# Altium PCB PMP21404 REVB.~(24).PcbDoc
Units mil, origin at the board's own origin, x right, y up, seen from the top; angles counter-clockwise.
Board outline 2750 x 3000 mil, 2 copper layers (Top Layer, Bottom Layer), stack 62 mil thick; 50 components, 25 nets, 104 pads, 31 vias.
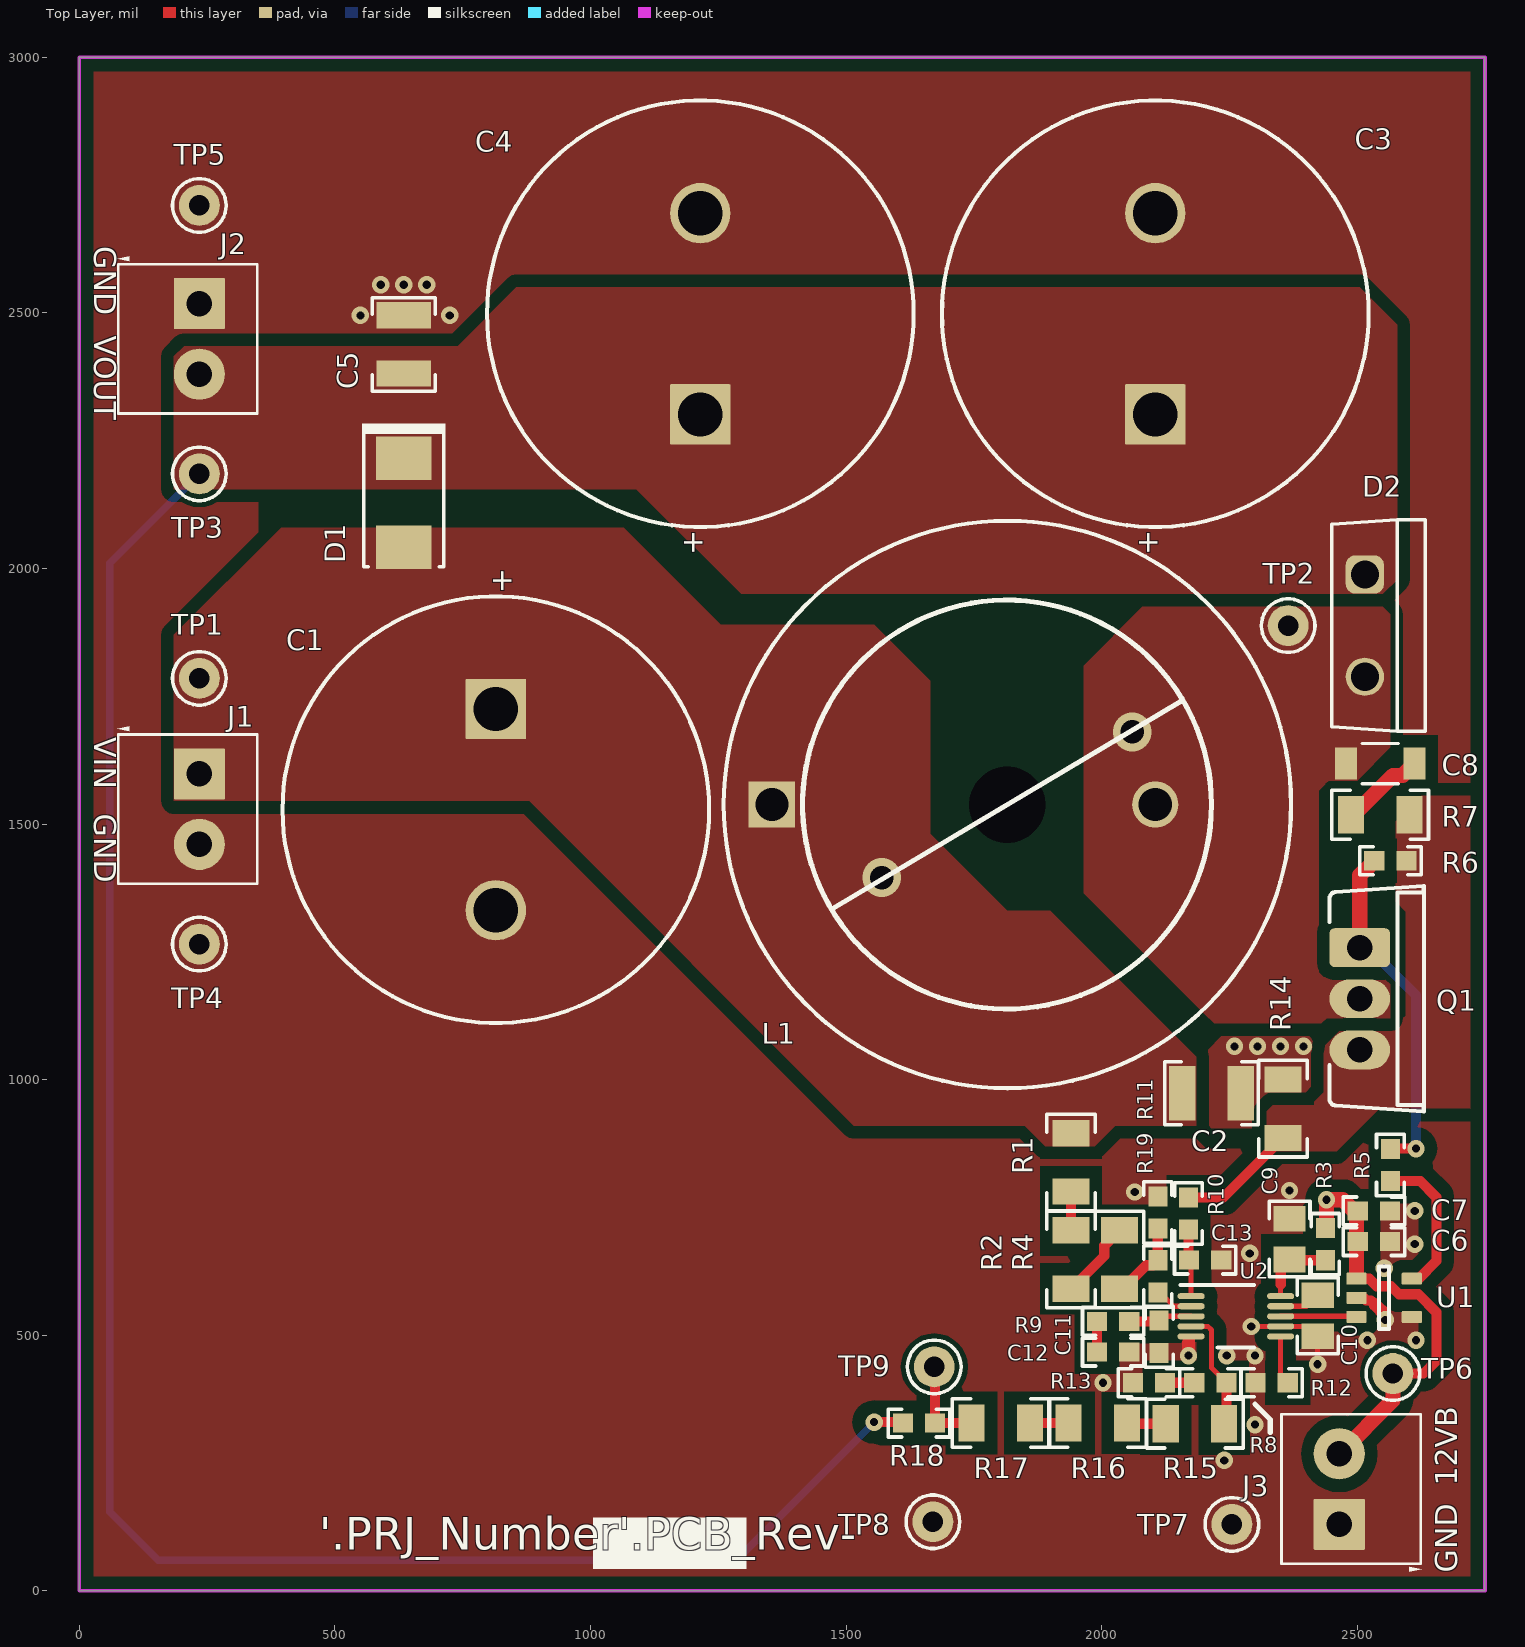
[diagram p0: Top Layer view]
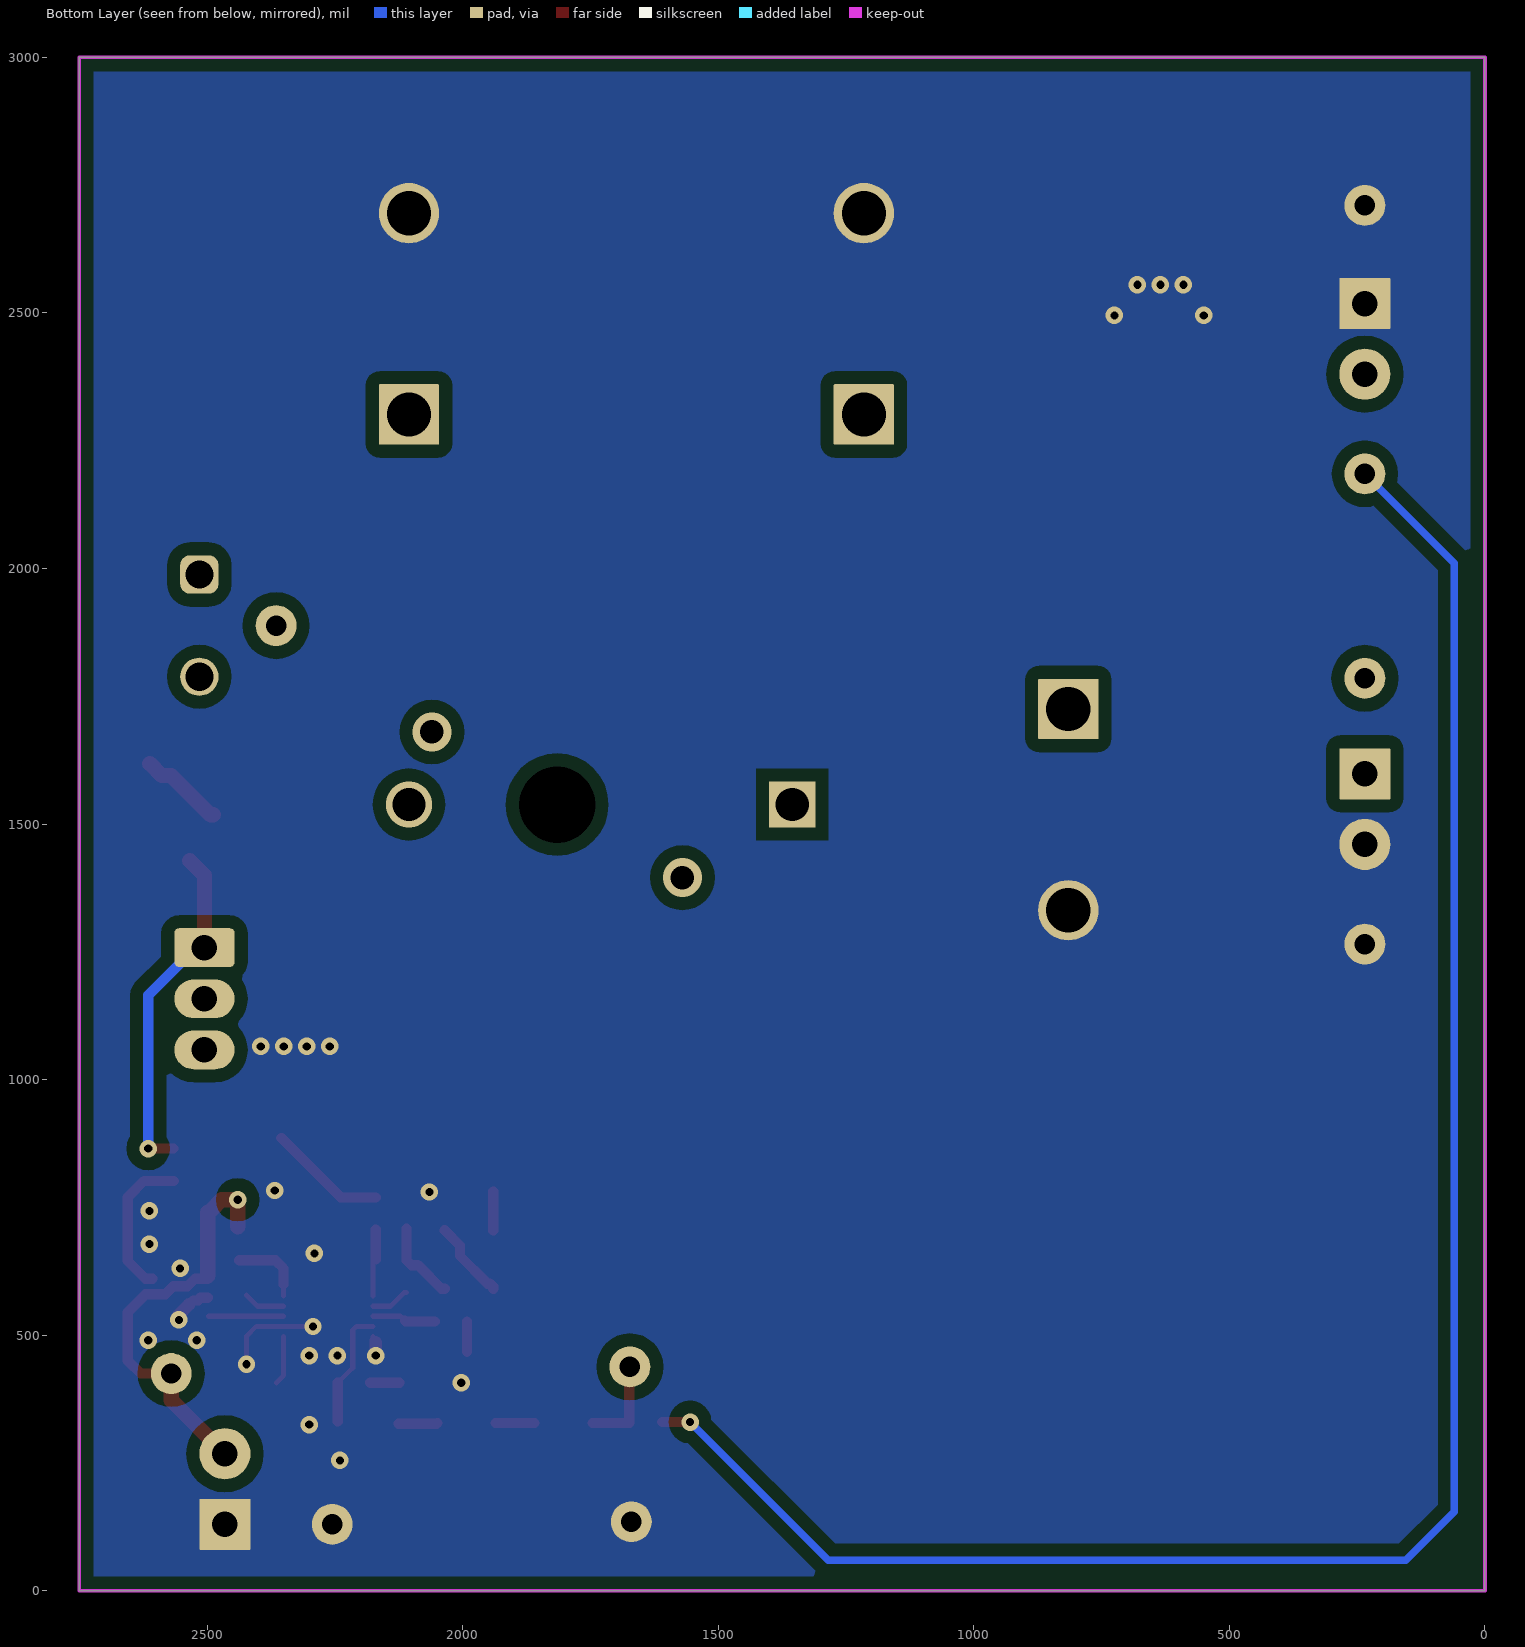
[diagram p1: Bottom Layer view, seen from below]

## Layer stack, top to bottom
Top Solder: solder mask 0.4, Solder Resist, Dk 3.5
Top Layer: signal copper 1.4
Dielectric1: core 59.2, FR-4, Dk 4.8
Bottom Layer: signal copper 1.4
Bottom Solder: solder mask 0.4, Solder Resist, Dk 3.5

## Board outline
0,0 2750,0 2750,3000 0,3000

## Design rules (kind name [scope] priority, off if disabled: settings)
AcuteAngle [All] p1: minimum=4.50000000000000E+0001 checktracksonly=FALSE
AssemblyTestPointUsage [All] p1: valid=2
BoardOutlineClearance BoardOutlineClearance_MountingHoles [OnCopper and InComponentClass('Mounting Holes')] p1: gap=40 ignorepadtopadclearanceinfootprint=FALSE
BoardOutlineClearance BoardOutlineClearance_Poly [OnCopper and IsPoly] p2: gap=25 ignorepadtopadclearanceinfootprint=FALSE
BoardOutlineClearance [OnCopper and Not InComponentClass('Logo') and not InComponentClass('FiducialMark') and not InRegion(1000,500,4000,800) and not InPoly] p3: gap=50 ignorepadtopadclearanceinfootprint=FALSE
Clearance Clearance_Keepouts [((IsTrack Or IsArc) And Not InPoly) And IsFree and IsKeepOut vs ((IsTrack Or IsArc) And Not InPoly) And IsFree and IsKeepOut] p1: gap=0 ignorepadtopadclearanceinfootprint=FALSE
Clearance Clearance_Poly [InPolygon] p2: gap=25 ignorepadtopadclearanceinfootprint=FALSE except(0: Arc-Hole Track-Hole SMDPad-Hole THPad-Hole Via-Hole Fill-Hole Poly-Hole Region-Hole Text-Hole)
Clearance Clearance_FiducialMark [IsKeepOut and InComponentClass('FiducialMark') vs IsPad and InComponentClass('FiducialMark')] p3: gap=0 ignorepadtopadclearanceinfootprint=FALSE
Clearance [All] p4: gap=7.87 ignorepadtopadclearanceinfootprint=FALSE except(0: Arc-Hole Track-Hole SMDPad-Hole THPad-Hole Via-Hole Fill-Hole Poly-Hole Region-Hole Text-Hole)
ComponentClearance ComponentClearance_MountingHoles_FiducialMarks [InComponentClass('Mounting Holes') vs InComponentClass('FiducialMark')] p1: gap=50 collisioncheckmode=3 verticalgap=10 showdistances=FALSE
ComponentClearance ComponentClearance_Shunt [InComponentClass('Header') vs InComponentClass('Shunt')] p2: gap=0 collisioncheckmode=3 verticalgap=0 showdistances=FALSE
ComponentClearance ComponentClearance_Logo [InComponentClass('Logo')] p3: gap=50 collisioncheckmode=3 verticalgap=10 showdistances=FALSE
ComponentClearance ComponentClearance_ScrewToNut [(HasFootprint('NY PMS 440 0025 PH')) vs (HasFootprint('Keystone_1902C'))] p4: gap=5 collisioncheckmode=3 verticalgap=10 showdistances=FALSE
ComponentClearance ComponentClearance_MountingHoles [InComponentClass('Mounting Holes')] p5: gap=250 collisioncheckmode=3 verticalgap=100000 showdistances=FALSE
ComponentClearance ComponentClearance_SmallPassives [HasFootprint('0201*') or HasFootprint('0402*') or HasFootprint('0508') or HasFootprint('0603*') or HasFootprint('0612') or HasFootprint('0805*') or HasFootprint('0815*') or HasFootprint('0830*') or HasFootprint('1206*') or HasFootprint('1210*') or HasFootprint('1808*') or HasFootprint('1812*') or HasFootprint('1825*') or HasFootprint('2010*') or HasFootprint('2220*') or HasFootprint('2225*') or HasFootprint('2512*') or HasFootprint('2728*') or HasFootprint('3518*') vs HasFootprint('0201*') or HasFootprint('0402*') or HasFootprint('0508') or HasFootprint('0603*') or HasFootprint('0612') or HasFootprint('0805*') or HasFootprint('0815*') or HasFootprint('0830*') or HasFootprint('1206*') or HasFootprint('1210*') or HasFootprint('1808*') or HasFootprint('1812*') or HasFootprint('1825*') or HasFootprint('2010*') or HasFootprint('2220*') or HasFootprint('2225*') or HasFootprint('2512*') or HasFootprint('2728*') or HasFootprint('3518*')] p6: gap=14.96 collisioncheckmode=3 verticalgap=10 showdistances=FALSE
ComponentClearance ComponentClearance_THtoSMT [IsThruComponent vs IsSMTComponent] p7: gap=40 collisioncheckmode=3 verticalgap=30 showdistances=FALSE
ComponentClearance ComponentClearance_THtoTH [IsThruComponent vs IsThruComponent] p8: gap=30 collisioncheckmode=3 verticalgap=30 showdistances=FALSE
ComponentClearance [All] p9: gap=30 collisioncheckmode=3 verticalgap=10 showdistances=FALSE
DiffPairsRouting [All] p1: maxlimit=100 minlimit=10 mostfreqgap=10 toplayer_minwidth=15 toplayer_maxwidth=15 toplayer_prefwidth=15 bottomlayer_minwidth=15 bottomlayer_maxwidth=15 bottomlayer_prefwidth=15 maxuncoupledlength=1000
FabricationTestPointUsage TestPointUsage [All] p1: valid=2 allowmultiple=FALSE
FabricationTestpoint Testpoint [All] p1: side=3 testpointundercomponent=TRUE minsize=40 maxsize=100 preferedsize=60 minholesize=0 maxholesize=40 preferedholesize=32 testpointgrid=1 allowsidetop=TRUE allowsidebottom=TRUE usegrid=TRUE gridtolerance=0.01
FanoutControl Fanout_LCC [IsLCC] p1: bgadir=Out bgaviamode=Centered fanoutstyle=Auto fanoutdirection=Alternating viagrid=1 // Fanout_LCC (Default Rule)
FanoutControl Fanout_BGA [IsBGA] p2: bgadir=Out bgaviamode=Centered fanoutstyle=Auto fanoutdirection=Alternating viagrid=1 // Fanout_BGA (Default Rule)
FanoutControl Fanout_Default [All] p4: bgadir=Out bgaviamode=Centered fanoutstyle=Auto fanoutdirection=Alternating viagrid=1 // Fanout_Default (Default Rule)
FanoutControl Fanout_Small [(CompPinCount < 5)] p5: bgadir=Out bgaviamode=Centered fanoutstyle=Auto fanoutdirection=OutThenIn viagrid=1 // Fanout_Small (Default Rule)
HoleSize [All] p1: absolutevalues=TRUE maxlimit=251 minlimit=7.87 maxpercent=80.000 minpercent=20.000
MinimumAnnularRing MinimumAnnularRing_ThermalPadVias [IsVia and InAnyComponent] p1: minimumring=5.91
MinimumAnnularRing [All] p2: minimumring=8
MinimumSolderMaskSliver MinimumSolderMaskSliver_Logo [InComponentClass('Logo') vs InComponentClass('Logo')] p1: minsoldermaskwidth=0.7
MinimumSolderMaskSliver [All] p2: minsoldermaskwidth=3.94
PlaneConnect [All] p1: planeconnectstyle=Direct reliefexpansion=10 reliefentries=4 reliefconductorwidth=10 reliefairgap=10
PolygonConnect [All] p1: connectstyle=Direct reliefconductorwidth=10 reliefentries=4 polygonreliefangle="90 Angle" airgapwidth=10
RoutingVias ThermalPadVias [IsVia and InAnyComponent] p1: holewidth=7.87 width=19.68 viastyle="Through Hole" minholewidth=7.87 minwidth=19.68 maxholewidth=12.99 maxwidth=23.62
RoutingVias [All] p2: holewidth=16 width=34 viastyle="Through Hole" minholewidth=7.87 minwidth=26 maxholewidth=40 maxwidth=65
SilkToBoardRegionClearance [Not ((IsComment or IsDesignator) And (Hide <> 'False')) and not InRegion(1000,500,4000,800)] p1:
SilkToSilkClearance SilkToSilkClearance_Pb-FreeLogo [(HasFootprint('Pb-Free_Overlay_Medium') OR HasFootprint('Pb-Free_Overlay_Small')) vs (HasFootprint('Pb-Free_Overlay_Medium') OR HasFootprint('Pb-Free_Overlay_Small'))] p1: silktosilkclearance=0
SilkToSilkClearance [All] p2: silktosilkclearance=0
SilkToSolderMaskClearance SilkToComponentPadClearance [(IsPad or IsFill or IsRegion) and InAnycomponent] p1: minsilkscreentomaskgap=0 clearancetoexposedcopper=TRUE
SilkToSolderMaskClearance "Silk to Solder Mask Opening" [All] p2: minsilkscreentomaskgap=0 clearancetoexposedcopper=FALSE
SolderMaskExpansion [All] p1: expansion=1.97
Width [All] p1: maxlimit=100 minlimit=6 preferedwidth=10 checkconnectedcopper=TRUE
15 further rules are at their usual default settings.

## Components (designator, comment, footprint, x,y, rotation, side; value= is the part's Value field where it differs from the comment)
C1 "LLS2W560MELY" Nichicon_2000x2500_Snap 815,1528.07 r270 top value=56uF
C2 "CGA6L1X7T2J104K160AC" 1210_200 2215,973.07 r0 top value=0.1uF
C3 "LLS2W560MELY" Nichicon_2000x2500_Snap 2105,2498.07 r90 top value=56uF
C4 "" Nichicon_2000x2500_Snap 1215,2498.07 r90 top
C5 "CGA6L1X7T2J104K160AC" 1210_200 635,2438.07 r90 top
C6 "C0603C104K5RACAUTO" 0603 2532.68,683.07 r0 top value=0.1uF
C7 "CGA3E1X7R1C105K080AC" 0603 2532.68,743.07 r0 top value=1uF
C8 "C3216C0G2E153J160AA" 1206_190 2545,1618.07 r0 top
C9 "CGA4J3X7R1H105K125AB" 0805_HV 2367.68,688.07 r90 top value=1uF
C10 "CGA4J3X7R1H105K125AB" 0805_HV 2422.68,538.07 r270 top value=1uF
C11 "GRM188R71H471KA01D" 0603 2112.68,496.93 r270 top value=470pF
C12 "CGA3E3X7R1H474K080AB" 0603 2022.68,466.93 r0 top value=0.47uF
C13 "GRM188R71H102JA01D" 0603 2202.68,646.93 r0 top value=1000pF
D1 "STTH3L06U" SMB 635,2128.07 r270 top value=600V
D2 "C3D03060A" TO-220-2 2515,1888.07 r270 top value=600V
J1 "Receptacle_2x1" TERM_BLK_ED555-2DS 235,1598.07 r270 top
J2 "Receptacle_2x1" TERM_BLK_ED555-2DS 235,2518.07 r270 top
J3 "Receptacle_2x1" TERM_BLK_ED555-2DS 2465,130 r90 top
L1 "RL-1256-3-470" Renco_RL1256-3_Pitch_750 1815,1538.07 r0 top value=470uH
Q1 "IPP60R299CPXKSA1" TO-220AB 2505,1158.07 r270 top value=600V
R1 "CRCW1206150KFKEA" 1206 1940,838.07 r90 top value=150k
R2 "CRCW1206150KFKEA" 1206 1940,648.07 r90 top value=150k
R3 "CRCW060310R0FKEA" 0603 2437.68,678.07 r270 top value=10.0
R4 "CRCW1206150KFKEA" 1206 2035,648.07 r90 top value=150k
R5 "CRCW06033R30JNEA" 0603 2565,833.07 r90 top value=3.3
R6 "CRCW0603100KFKEA" 0603 2565,1428.07 r180 top value=100k
R7 "CRCW1206150KFKEA" 1206 2545,1518.07 r0 top
R8 "RG1608P-2611-B-T5" 0603 2212.68,406.93 r0 top value=2.61k
R9 "CRCW060310K0FKEA" 0603 2022.68,526.93 r0 top value=10.0k
R10 "Resistor" 0603 2170,738.07 r270 top value=221
R11 "RT0603BRD074K59L" 0603 2110,740 r270 top value=4.59k
R12 "CRCW0603169KFKEA" 0603 2332.68,406.93 r0 top value=169k
R13 "RMCF0603ZT0R00" 0603 2092.68,406.93 r0 top value=0
R14 "WSLP1206R0150FEA" 1206 2355,943.07 r270 top value=0.015
R15 "CRCW1206150KFKEA" 1206 2182.68,326.93 r0 top value=150k
R16 "CRCW1206150KFKEA" 1206 1992.68,328.07 r0 top value=150k
R17 "CRCW1206150KFKEA" 1206 1802.68,328.07 r0 top value=150k
R18 "Resistor" 0603 1642.68,328.07 r0 top value=49.9
R19 "RMCF0603ZT0R00" 0603 2110,615 r90 top value=0
TP1 "5000" Keystone5000 235,1785 r90 top
TP2 "5000" Keystone5000 2365,1888.07 r90 top
TP3 "5000" Keystone5000 235,2185 r90 top
TP4 "5001" Keystone5001 235,1265 r90 top
TP5 "5001" Keystone5001 235,2710 r90 top
TP6 "5000" Keystone5000 2570,425 r0 top
TP7 "5001" Keystone5001 2255,130 r0 top
TP8 "5001" Keystone5001 1670,135 r90 top
TP9 "5000" Keystone5000 1672.68,438.07 r90 top
U1 "UCC27517AQDBVRQ1" DBV0005A_N 2552.68,573.07 r0 top
U2 "LM3481QMM/NOPB" DGS0010A_N 2262.68,536.93 r0 top

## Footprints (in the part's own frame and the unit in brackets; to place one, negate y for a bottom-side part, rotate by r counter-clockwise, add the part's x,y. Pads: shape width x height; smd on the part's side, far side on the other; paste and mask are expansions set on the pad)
0603 [mm] "0603 from SM-752 data"
  rect 1x0.95 smd: 1(-0.8,0) 2(0.8,0)
  silkscreen extent -1.52,-0.69 1.52,0.69, body extent -0.87,-0.47 0.87,0.47, height 1
0805_HV [mil] "0805 with 30mil clearance between pads"
  rect 50x63 smd: 1(-40,0) 2(40,0)
  silkscreen extent -74,-40 74,40, body extent -43,-29 43,29, height 57
1206 [mm] "1206 from SM-752 data"
  rect 1.3x1.85 smd: 1(-1.45,0) 2(1.45,0)
  silkscreen extent -2.4,-1.21 2.4,1.21, body extent -1.7,-0.9 1.7,0.9, height 1.35
1206_190 [mm] "1206_190"
  rect 1.1x1.6 smd: 1(-1.7,0) 2(1.7,0)
  silkscreen extent -0.9,-1 0.9,1, body extent -1.75,-0.95 1.75,0.95, height 1.9
1210_200 [mm] "1210"
  rect 1.3x2.7 smd: 1(-1.45,0) 2(1.45,0)
  silkscreen extent -2.32,-1.57 2.32,1.57, body extent -1.7,-1.35 1.7,1.35, height 2
DBV0005A_N [mm] "SOT23, 5-Leads, Body 2.9x1.6mm, Pitch 0.95mm, Lead Span 2.8mm, IPC Medium Density"
  rrect17% 1x0.6 smd: 1(-1.375,0.95) 2(-1.375,0) 3(-1.375,-0.95) 4(1.375,-0.95) 5(1.375,0.95)
  silkscreen extent -0.25,-1.55 0.25,1.55, body extent -1.42,-1.46 1.42,1.46, height 1.09
DGS0010A_N [mm] "TSSOP, 10-Leads, Body 3x3mm, Pitch 0.5mm, IPC Medium Density"
  oval 1.35x0.3 smd: 1(-2.225,1) 2(-2.225,0.5) 3(-2.225,0) 4(-2.225,-0.5) 5(-2.225,-1) 6(2.225,-1) 7(2.225,-0.5) 8(2.225,0) 9(2.225,0.5) 10(2.225,1)
  silkscreen extent -2.75,-1.55 0.9,1.55, body extent -2.45,-1.5 2.45,1.5, height 0.96
Keystone5000 [mil] "For Keystone 500x miniature loop terminals"
  round 80 hole 40: 1(0,0)
  silkscreen extent -52,-52 52,52, body extent -49,-49 49,49, height 182
Keystone5001 [mil] "For Keystone 500x miniature loop terminals"
  round 80 hole 40: 1(0,0)
  silkscreen extent -52,-52 52,52, body extent -49,-49 49,49, height 182
Nichicon_2000x2500_Snap [mm]
  rrect3% 3x3 hole 2.2: 1(-5,0)
  round 3 hole 2.2: 2(5,0)
  silkscreen extent -10.6,-10.6 10.6,10.6, body extent -10.5,-10.5 10.51,10.5, height 27.01
Renco_RL1256-3_Pitch_750 [mm] "RENCO"
  rect 2.3x2.3 hole 1.65 paste+0 mask+0.05: 1(-11.684,0)
  round 2.3 hole 1.65 paste+0 mask+0.05: 2(7.366,0)
  round 1 hole 3.8 unplated: MH(0,0)
  silkscreen extent -14.08,-14.1 14.11,14.1, body extent -13.97,-13.97 13.97,13.97, height 21.59
SMB [mil] "Molded Diode, 2-Leads, Body 5.4x3.6mm, IPC Medium Density, based on OnSemi component dimensions"
  rect 85x107.99 smd: 1(-87.01,0) 2(87.01,0)
  silkscreen extent -155,-82 125,82, body extent -106,-71 106,71, height 91
TERM_BLK_ED555-2DS [mil]
  rrect4% 100x100 hole 50: 1(0,0)
  round 100 hole 50: 2(138,0)
  silkscreen extent -93,-161 215,113, body extent -69,-150 207,106, height 323
TO-220-2 [mm] "CREE"
  rrect50% 1.9x1.9 hole 1.4: 1(-2.54,0)
  round 1.9 hole 1.4: 2(2.54,0)
  silkscreen extent -5.25,-1.64 5.26,3.01, body extent -5.21,-1.57 5.21,3.12, height 19.47
TO-220AB [mil] "Copied from Altium's version of TO3B"
  rrect25% 76x118.11 hole 50: 1(-100,0)
  oval 76x118.11 hole 50: 2(0,0) 3(100,0)
  silkscreen extent -221,-59 221,126, body extent -221,-59 221,126, height 765

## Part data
C1 C3: library part CMP-0010119-2, "CAP, AL, 56 uF, 450 V, +/- 20%, TH", Cap_Case=20x25mm, Manufacturer=Nichicon, Supplier Part Number 1=493-2592-ND, Tolerance_%=20%, Value1=Unknown, Value2=450V, ValueDisplayed=56uF
C2: library part CMP-0009140-2, "CAP, CERM, 0.1 uF, 630 V, +/- 10%, X7R, AEC-Q200 Grade 1, 1210", Cap_Case=1210, Manufacturer=TDK, Supplier Part Number 1=445-7116-1-ND, TempCo=X7R, Tolerance_%=10%, Value1=Unknown, Value2=630V, ValueDisplayed=0.1uF
C4: library part CMP-0010119-2, "CAP, AL, DNP", Cap_Case=20x25mm, Tolerance_%=20%, Value1=Unknown, ValueDisplayed=DNP
C5: library part CMP-0009140-2, "CAP, CERM, DNP", Cap_Case=1210, Value1=Unknown, ValueDisplayed=DNP
C6: library part CMP-0079602-1, "CAP, CERM, 0.1 µF, 50 V,+/- 10%, X7R, AEC-Q200 Grade 1, 0603", Cap_Case=0603, Manufacturer=Kemet, Supplier Part Number 1=399-6856-1-ND, TempCo=X7R, Tolerance_%=10%, Value2=50V, ValueDisplayed=0.1µF
C7: library part CMP-0079607-1, "CAP, CERM, 1 µF, 16 V,+/- 10%, X7R, AEC-Q200 Grade 1, 0603", Cap_Case=0603, Manufacturer=TDK, Supplier Part Number 1=445-12539-1-ND, TempCo=X7R, Tolerance_%=10%, Value2=16V, ValueDisplayed=1µF
C8: library part CMP-0008644-2, "CAP, CERM, DNP", Cap_Case=1206, Value1=Unknown, ValueDisplayed=DNP
C9 C10: library part CMP-0007976-2, "CAP, CERM, 1 uF, 50 V, +/- 10%, X7R, AEC-Q200 Grade 1, 0805", Cap_Case=0805, Manufacturer=TDK, Supplier Part Number 1=445-6961-1-ND, TempCo=X7R, Tolerance_%=10%, Value1="0.008782 ohm", Value2=50V, ValueDisplayed=1uF
C11: library part CMP-0007455-4, "CAP, CERM, 470 pF, 50 V, +/- 10%, X7R, 0603", Cap_Case=0603, Manufacturer=MuRata, Supplier Part Number 1=490-1489-1-ND, TempCo=X7R, Tolerance_%=10%, Value1=Unknown, Value2=50V, ValueDisplayed=470pF
C12: library part CMP-0007096-4, "CAP, CERM, 0.47 uF, 50 V, +/- 10%, X7R, AEC-Q200 Grade 1, 0603", Cap_Case=0603, Manufacturer=TDK, Supplier Part Number 1=810-CGA3E3X7R1H474K080AB, TempCo=X7R, Tolerance_%=10%, Value1="0.01064 ohm", Value2=50V, ValueDisplayed=0.47uF
C13: library part CMP-0007431-4, "CAP, CERM, 1000 pF, 50 V, +/- 5%, X7R, 0603", Cap_Case=0603, Manufacturer=MuRata, Supplier Part Number 1=490-9733-1-ND, TempCo=X7R, Tolerance_%=5%, Value1=Unknown, Value2=50V, ValueDisplayed=1000pF
D1: library part CMP-0077014-1, "Diode, Ultrafast, 600 V, 3 A, SMB", Manufacturer=STMicroelectronics, Supplier Part Number 1=497-3771-1-ND, Value1=3A, Value2=1.3V
D2: library part CMP-0079543-1, "Diode, Schottky, 600 V, 11 A, AEC-Q101, TH", Manufacturer=Cree, Supplier Part Number 1=941-C3D03060A, Value1=11A, Value2=V
J1 J2 J3: library part CMP-0074913-1, "Terminal Block, 3.5mm Pitch, 2x1, TH", Color=Grey, Current_A=6A, Manufacturer="On-Shore Technology", PartNumber=ED555/2DS, Supplier Part Number 1=ED1514-ND, Voltage_V=150V
L1: library part CMP-0077831-1, "Inductor, 470 µH, 4 A, 0.187 ohm, TH", Manufacturer="Renco Electronics", Value1="0.187 ohm", Value2=4A, ValueDisplayed=470µH
Q1: library part CMP-0001176-3, "MOSFET, N-CH, 600 V, 11 A, TO-220AB", Alternate Manufacturer=None, Manufacturer="Infineon Technologies", Supplier Part Number 1=IPP60R299CPXKSA1-ND, Value2="22 nC"
R1 R2 R4 R15 R16 R17: library part CMP-0016639-3, "RES, 150 k, 1%, 0.25 W, AEC-Q200 Grade 0, 1206", Manufacturer=Vishay-Dale, Power_W=250mW, Supplier Part Number 1=541-150KFCT-ND, TempCo="100 ppm/C", Tolerance_%=1%, Value2=0.25W, Value_Code=150k
R3: library part CMP-0022003-4, "RES, 10.0, 1%, 0.1 W, AEC-Q200 Grade 0, 0603", Manufacturer=Vishay-Dale, Power_W=100mW, Supplier Part Number 1=541-10.0HCT-ND, TempCo="100 ppm/C", Tolerance_%=1%, Value2=0.1W, Value_Code=10R0, ValueDisplayed=10.0
R5: library part CMP-0025805-4, "RES, 3.3, 5%, 0.1 W, AEC-Q200 Grade 0, 0603", Manufacturer=Vishay-Dale, Power_W=100mW, Supplier Part Number 1=541-3.3GCT-ND, TempCo="200 ppm/C", Tolerance_%=5%, Value2=0.1W, Value_Code=3R30, ValueDisplayed=3.3
R6: library part CMP-0021990-4, "RES, 100 k, 1%, 0.1 W, AEC-Q200 Grade 0, 0603", Manufacturer=Vishay-Dale, Power_W=100mW, Supplier Part Number 1=541-100KHCT-ND, TempCo="100 ppm/C", Tolerance_%=1%, Value2=0.1W, Value_Code=100k
R7: library part CMP-0016639-3, "RES, DNP, 1206", TempCo="100 ppm/C", ValueDisplayed=DNP
R8: library part CMP-0023494-3, "RES, 2.61 k, 0.1%, 0.1 W, 0603", Manufacturer="Susumu Co Ltd", Power_W=100mW, Supplier Part Number 1=RG16P2.61KBCT-ND, TempCo="25 ppm/C", Tolerance_%=0.1%, Value2=0.1W, Value_Code=2k61, ValueDisplayed=2.61k
R9: library part CMP-0021998-4, "RES, 10.0 k, 1%, 0.1 W, AEC-Q200 Grade 0, 0603", Manufacturer=Vishay-Dale, Power_W=100mW, Supplier Part Number 1=541-10.0KHCT-ND, TempCo="100 ppm/C", Tolerance_%=1%, Value2=0.1W, Value_Code=10k0, ValueDisplayed=10.0k
R10: library part CMP-0022217-5, "RES, 221, 1%, 0.1 W, AEC-Q200 Grade 0, 0603", Manufacturer=Vishay-Dale, PartNumber=CRCW0603221RFKEA, Power_W=100mW, Supplier Part Number 1=541-221HCT-ND, TempCo="100 ppm/C", Tolerance_%=1%, Value2=0.1W, Value_Code=221R, ValueDisplayed=221
R11: library part CMP-0024297-2, "RES, 4.59 k, 0.1%, 0.1 W, 0603", Manufacturer="Yageo America", Power_W=100mW, TempCo="25 ppm/C", Tolerance_%=0.1%, Value2=0.1W, Value_Code=4k59, ValueDisplayed=4.59k
R12: library part CMP-0022077-4, "RES, 169 k, 1%, 0.1 W, AEC-Q200 Grade 0, 0603", Manufacturer=Vishay-Dale, Power_W=100mW, Supplier Part Number 1=541-169KHCT-ND, TempCo="100 ppm/C", Tolerance_%=1%, Value2=0.1W, Value_Code=169k
R13 R19: library part CMP-0023343-3, "RES, 0, 1%, 0.1 W, AEC-Q200 Grade 0, 0603", Manufacturer="Stackpole Electronics Inc", Power_W=100mW, Supplier Part Number 1=RMCF0603ZT0R00CT-ND, TempCo=ppm/C, Tolerance_%=1%, Value2=0.1W, Value_Code=0
R14: library part CMP-0018571-2, "RES, 0.015, 1%, 1 W, 1206", Manufacturer=Vishay-Dale, Power_W=1W, Supplier Part Number 1=WSLP-.015CT-ND, TempCo="75 ppm/C", Tolerance_%=1%, Value_Code=R015, ValueDisplayed=0.015
R18: library part CMP-0022448-4, "RES, 49.9, 1%, 0.1 W, AEC-Q200 Grade 0, 0603", Manufacturer=Vishay-Dale, PartNumber=CRCW060349R9FKEA, Power_W=100mW, Supplier Part Number 1=541-49.9HCT-ND, TempCo="100 ppm/C", Tolerance_%=1%, Value2=0.1W, Value_Code=49R9, ValueDisplayed=49.9
TP1 TP2 TP3 TP6 TP9: library part CMP-0055137-1, "Test Point, Miniature, Red, TH", Color=Red, Manufacturer=Keystone, Supplier Part Number 1=36-5000-ND
TP4 TP5 TP7 TP8: library part CMP-0055138-1, "Test Point, Miniature, Black, TH", Color=Black, Manufacturer=Keystone, Supplier Part Number 1=36-5001-ND
U1: library part CMP-0066947-1, "4A/4A Single Channel High-speed Low-side Gate Driver, DBV0005A (SOT-23-5)", Alternate Manufacturer="Texas Instruments"
U2: library part CMP-0071928-2, "High Efficiency Low-Side N-Channel Controller for Switching Regulators, AEC-Q100 Grade 1, 10-pin Mini SOIC, 1000 Reel", Alternate Manufacturer="Texas Instruments", Alternate PartNumber=LM3481QMMX/NOPB

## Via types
v1: diameter 34, hole 16, Top Layer to Bottom Layer, 29 vias
v2: diameter 76, hole 46, Top Layer to Bottom Layer, 2 vias

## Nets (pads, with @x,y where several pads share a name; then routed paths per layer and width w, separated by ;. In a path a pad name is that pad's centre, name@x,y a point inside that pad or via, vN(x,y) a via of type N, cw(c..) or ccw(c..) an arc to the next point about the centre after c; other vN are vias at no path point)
GND: C1.2 C2.2 C3.2 C4.2 C5.2 C6.2 C7.2 C9.2 C10.2 C11.2 C12.2 C13.2 J1.2 J2.1 J3.1 R11.1 R12.1 R13.1 R14.1 TP4.1 TP5.1 TP7.1 TP8.1 U1.2 U1.4 U2.5 U2.7 | length 313.6
  Top Layer w10: 2175.08,490.97 U2.5 ; v1(2292.68,516.93) 2292.99,517.25 U2.7 2403.5,517.25 C10.2 v1(2422.68,443.07)
  Top Layer w15: 2170,485.89 2175.08,490.97
  Top Layer w20: U1.2 2513.07,573.07 2513.07,571.93 2517.18,567.82 2527.18,567.82 2535,560
  Top Layer w25: v1(2170,460) 2170,485.89 ; 2535,560 2555,540 v1(2555,530)
  other v1: 2240,255 2300,325 2002.68,406.93 2245,460 2300,460 2520,490 2615,490 2552.68,630.57 2290,660 2612.68,678.07 2612.68,743.07 2065,780 2367.68,783.07 2260,1065 2305,1065 2350,1065 2395,1065 550,2495 725,2495 590,2555 635,2555 680,2555
NetC1_1: C1.1 C2.1 D1.2 J1.1 L1.1 R1.2 TP1.1
  other v2: 1570,1395
NetC3_1: C3.1 C4.1 C5.1 D1.1 D2.1 J2.2 R18.1 TP3.1 | length 3802.9
  Top Layer w20: v1(1555,330) R18.1@1609.25,330
  Bottom Layer w15: TP3.1 60,2010 60,155 155,60 1285,60 v1(1555,330)
NetC6_1: C6.1 C7.1 J3.2 R3.1 TP6.1 U1.1 | length 820.2
  Top Layer w20: U1.1@2498.54,616.42 U1.1 2523.46,610.47 2538.24,595.7 2565.99,595.7 2581.69,580 2620,580 2655,545 2655,450 2630,425 TP6.1
  Top Layer w30: R3.1@2440,711.89 v1(2440,765) 2471.65,765 C7.1@2493.58,743.07 ; J3.2 2570,373 TP6.1 ; U1.1@2498.54,616.42 C7.1@2498.54,740.43
NetC8_1: C8.1 D2.2 L1.2 Q1.2 TP2.1
  other v2: 2060,1680
NetC8_2: C8.2 R7.1 | length 165.4
  Top Layer w30: R7.1 2493.07,1518.07 2570,1595 2588.86,1595 C8.2
NetC9_1: C9.1 R3.2 U2.10 | length 148.4
  Top Layer w10: U2.10 2350.28,599.72
  Top Layer w20: 2350.28,599.72 2350.28,630.67 2366.18,646.57 R3.2
NetC10_1: C10.1 U2.9 | length 81.3
  Top Layer w10: U2.9 2401.22,556.62 C10.1
NetC11_1: C11.1 R9.2 U2.3 | length 125
  Top Layer w10: C11.1 2121.18,536.93 U2.3
  Top Layer w20: R9.2 2111.18,526.93 C11.1
NetC12_1: C12.1 R9.1 | length 60
  Top Layer w20: C12.1 R9.1
NetC13_1: C13.1 R10.2 U2.1 | length 132.4
  Top Layer w10: C13.1@2170,648.11 C13.1 2175.08,643.03 U2.1
  Top Layer w20: C13.1@2170,648.11 R10.2
NetQ1_1: Q1.1 R5.2 R6.2 | length 679.9
  Top Layer w20: R5.2@2565.43,865 v1(2615,865)
  Top Layer w30: Q1.1 2505,1399.57 R6.2
  Bottom Layer w20: Q1.1 2521.93,1258.07 2615,1165 v1(2615,865)
NetQ1_3: Q1.3 R6.1 R7.2 R10.1 R14.2 | length 233.2
  Top Layer w20: R10.1 2238.58,769.57 R14.2
NetR1_1: R1.1 R2.2 | length 75.8
  Top Layer w20: R2.2 R1.1
NetR2_1: R2.1 R4.2 | length 156.2
  Top Layer w20: R2.1 1940,594.57 1946.26,600.83 1950.83,600.83 2005,655 2005,675.16 R4.2
NetR4_1: R4.1 R11.2 R19.2 | length 160
  Top Layer w20: R4.1 2041.42,590.98 2087.07,636.63 2099.98,636.63 2109.84,646.5 R19.2 R11.2
NetR5_1: R5.1 U1.5 | length 290.6
  Top Layer w20: R5.1 2623.43,801.57 2655,770 2655,645 2620.47,610.47 U1.5
NetR8_1: R8.1 R13.2 | length 57
  Top Layer w20: R13.2 R8.1
NetR8_2: R8.2 R15.2 U2.4 | length 233.7
  Top Layer w10: U2.4 2207.75,517.25 2215,510 2215,436.1 R8.2
  Top Layer w20: R15.2@2244.17,331.34 R8.2
NetR12_2: R12.2 U2.6 | length 96.4
  Top Layer w10: U2.6 2350.28,420.83 R12.2
NetR15_1: R15.1 R16.2 | length 76.3
  Top Layer w20: R16.2 2050.9,326.93 R15.1
NetR16_1: R16.1 R17.2 | length 75.8
  Top Layer w20: R17.2 R16.1
NetR17_1: R17.1 R18.2 TP9.1 | length 182
  Top Layer w20: TP9.1 1674.17,436.57 R18.2 R17.1
NetR19_1: R19.1 U2.2 | length 76.2
  Top Layer w10: R19.1 2114.19,583.5 2141.08,556.62 U2.2
NetU1_3: U1.3 U2.8 | length 147
  Top Layer w10: U2.8 U1.3@2497.28,536.93
pads on no net: L1.MH

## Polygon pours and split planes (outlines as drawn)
NetC1_1 on Top Layer "TOP_LAYER_NETC1_1_P002" (solid, remove dead copper, pour order 2): 185,1545 185,1870 395,2080 1065,2080 1815,1330 1900,1330 2185,1045 2185,910.08 2026.34,910.08 1986.26,870 1890,870 1850,910 1515,910 880,1545
NetC8_1 on Top Layer "TOP_LAYER_NETC8_1_P004" (solid, remove dead copper, pour order 4): 2565,1120 2210,1120 1965,1365 1965,1810 2080,1925 2550,1925 2565,1910 2565,1650 2500,1585 2445,1585 2425,1565 2425,1210 2435,1200 2563.83,1200 2565,1198.83
NetC8_1 on Top Layer "TOP_LAYER_NETC8_1_P006" (solid, remove dead copper, pour order 6): 2505,1120 2440,1120 2430,1110 2220,1110 2190,1140 2190,1155 2195,1150 2505,1150
NetC3_1 on Top Layer "TOP_LAYER_NETC3_1_P008" (solid, remove dead copper, pour order 8): 2550,1950 2578.29,1978.29 2578.29,2476.71 2505,2550 855,2550 740,2435 205,2435 185,2415 185,2155 1090,2155 1295,1950
NetQ1_3 on Top Layer "TOP_LAYER_NETQ1_3_P010" (solid, remove dead copper, pour order 10): 2320,860 2320,935 2335,950 2410,950 2435,975 2435,1065 2465,1095 2565,1095 2595,1125 2595,1328.83 2575,1348.83 2575,1505 2625,1555 2750,1555 2750,945 2748.38,943.38 2582.55,943.38 2582.45,943.28 2543.28,943.28 2460,860
NetC1_1 on Top Layer "TOP_LAYER_NETC1_1_P014" (solid, remove dead copper, pour order 14): 1245,1890 1555,1890 1665,1780 1665,1425 1660,1420 1245,1420
GND on Top Layer "TOP_LAYER_GND_P016" (solid, remove dead copper, pour order 16): 0,0 0,3000 2750,3000 2750,0
GND on Bottom Layer "BOTTOM_LAYER_GND_P012" (solid, remove dead copper, pour order 12): 0,0 0,3000 2750,3000 2750,0

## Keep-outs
Keep-Out Layer:
  the board outline again, w7
  text ".Layer_Name" at 577,-858.49 h60

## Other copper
Top Layer:
  pour cut-out: 2200,905 2305,905 2305,865 2205,865 2170,900 2195,900
  pour cut-out: 350,2060 350,2145 440,2145 440,2100 390,2100
  pour cut-out: 2210,1035 2208.55,1036.45 2208.55,1058.55 2235,1085 2235,1100 2180,1100 2165,1085
  text ".Layer_Name" at 577,-858.49 h60
Bottom Layer:
  text ".Layer_Name" at 577,-858.49 h60

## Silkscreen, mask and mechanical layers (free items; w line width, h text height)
Top Overlay:
  circle w10: c1815,1538.07 r400
  region: 1305,143.07 1005,143.07 1005,43.07 1305,43.07
  lines w10: 1475,1335 2155,1740 ; 2300,365 2330,335 2330,310
  text "GND" at 15,2630 h72.83 r270
  text "VOUT" at 15,2455 h72.83 r270
  text "VIN" at 15,1670 h72.83 r270
  text "GND" at 15,1520 h72.83 r270
  text "12VB" at 2710,205 h72.83 r90
  text "'.PRJ_Number'.PCB_Rev-" at 470,58.84 h108.27
  text "GND" at 2710,35 h72.83 r90
  text ".Layer_Name" at 577,-858.49 h60
Bottom Overlay:
  text ".Layer_Name" at 577,-858.49 h60
Top Paste:
  text ".Layer_Name" at 577,-858.49 h60
Bottom Paste:
  text ".Layer_Name" at 577,-858.49 h60
Top Solder:
  text ".Layer_Name" at 577,-858.49 h60
  text ".Layer_Name" at 577,-858.49 h60
Bottom Solder:
  text ".Layer_Name" at 577,-858.49 h60
Drill Guide:
  text ".Layer_Name" at 577,-858.49 h60
M1 Board Outline:
  lines w5: 0,0 2750,0 2750,3000 0,3000 0,0
  lines w7: 0,0 2750,0 2750,3000 0,3000 0,0
  text ".Layer_Name" at 577,-858.49 h60
M2 Board Dimensions:
  rectangle: 125,-400 500,-275
  rectangle: 0,-275 125,-150
  lines w7: 0,-275 1000,-275 ; 125,-400 125,-150 ; 250,-400 250,-150 ; 500,-400 500,-150 ; 750,-400 750,-150 ; 0,-400 0,-150 1000,-150 1000,-400 0,-400
  text ".Layer_Name" at 577,-858.49 h60
M3 3D STEP Top:
  text ".Layer_Name" at 577,-858.49 h60
M4 3D STEP Bottom:
  text ".Layer_Name" at 577,-858.49 h60
M5 Assembly Top:
  lines w10: -292,-930.17 6308,-930.17 ; -292,-726.83 6310,-726.83 ; -292,-523.5 -292,-1133.5 3713,-1133.5 6310,-1133.5 6310,-523.5 -291.5,-523.5 -291.5,-1133.5 1284,-1133.5 ; 2173,-1133.5 2173,-523.5 ; 3440,-726.83 3440,-523.5 ; 4280,-726.83 4280,-523.5 ; 4902,-1140 4902,-937.17
  text "COMPONENTS MARKED 'DNP' SHOULD NOT BE POPULATED." at 1153.5,-318.5 h60
  text "ASSEMBLY VARIANT:" at 1153,-434 h60
  text ".VariantName" at 2189,-434 h60
  text "PCB VIEWED FROM TOP SIDE" at -228.5,-655.67 h60
  text "BOARD #:" at 2248,-655.67 h60
  text ".PRJ_Number" at 2793.5,-655.67 h60
  text "REV:" at 3638,-655.67 h60
  text ".PCB_Rev" at 3929.5,-655.67 h60
  text "SVN REV:" at 4476,-655.67 h60
  text ".VersionControl_RevNumber" at 4982,-655.67 h60
  text "TID #:" at 2248,-859 h60
  text ".TID" at 2793.5,-859 h60
  text "PLOT NAME =" at -228.5,-1064.34 h60
  text ".plot_File_Name" at 577,-1064.34 h60
  text "GENERATED    :" at 2250,-1064.34 h60
  text ".Print_Date" at 3119.5,-1064.34 h60
  text ".Print_Time" at 3848.5,-1064.34 h60
  text "TEXAS INSTRUMENTS" at 5113,-1064.34 h60
M6 Assembly Bottom:
  lines w10: -292.5,-727.33 6309.5,-727.33 ; -290.5,-930.67 6309.5,-930.67 ; 1115.5,-1140.5 1115.5,-937.67 ; 1737.5,-727.33 1737.5,-524 ; 2577.5,-727.33 2577.5,-524 ; 3844.5,-1134 3844.5,-524 ; 4733.5,-1134 6309,-1134 6309,-524 -292.5,-524 -292.5,-1134 2304.5,-1134 6309.5,-1134 6309.5,-524
  text "COMPONENTS MARKED 'DNP' SHOULD NOT BE POPULATED." at 6102,-318 h60
  text ".VariantName" at 5058,-434 h60
  text "ASSEMBLY VARIANT:" at 6097,-434 h60
  text ".VersionControl_RevNumber" at 1035.5,-656.17 h60
  text "SVN REV:" at 1541.5,-656.17 h60
  text ".PCB_Rev" at 2088,-656.17 h60
  text "REV:" at 2379.5,-656.17 h60
  text ".PRJ_Number" at 3224,-656.17 h60
  text "BOARD #:" at 3769.5,-656.17 h60
  text "PCB VIEWED FROM BOTTOM SIDE" at 6246,-656.17 h60
  text ".TID" at 3224,-859.5 h60
  text "TID #:" at 3769.5,-859.5 h60
  text "TEXAS INSTRUMENTS" at 904.5,-1064.84 h60
  text ".Print_Time" at 2169,-1064.84 h60
  text ".Print_Date" at 2898,-1064.84 h60
  text "GENERATED    :" at 3767.5,-1064.84 h60
  text ".plot_File_Name" at 5440.5,-1064.84 h60
  text "PLOT NAME =" at 6246,-1064.84 h60
M9 Title Sheet:
  drawing of 57 lines, arcs and shapes, not listed
  text "1" at 739.84,8036.5 h70
  text "2" at 3235.5,8036.5 h70
  text "3" at 5724.84,8036.5 h70
  text "4" at 8231.51,8036.5 h70
  text "5" at 10730.5,8036.5 h70
  text "6" at 13235.5,8036.5 h70
  text "A" at -416.5,6893.5 h70
  text "A" at 14383.5,6893.5 h70
  text "B" at -416.5,4513.5 h70
  text "B" at 14383.5,4513.5 h70
  text "C" at -416.5,2138.5 h70
  text "C" at 14383.5,2138.5 h70
  text "PROJECT TITLE:" at 11343.5,277.5 h45
  text ".PRJ_Title" at 11393.5,144.17 h70
  text "DESIGNED FOR:" at 11343.5,-23.5 h45
  text ".PRJ_Customer" at 11393.5,-163.5 h70
  text "D" at -416.5,-231.5 h70
  text "D" at 14383.5,-231.5 h70
  text "FILE NAME:" at 11343.5,-323.5 h45
  text ".PCB_File_Name_No_Path" at 11393.5,-443.5 h70
  text "Texas Instruments (TI) and/or its licensors do not warrant the accuracy or completeness of this specification" at 6374,-605.34 h45
  text "ENGINEER:" at 11343.5,-613.5 h45
  text "LAYOUT BY:" at 12848.5,-613.5 h45
  text "or any information contained therein. TI and/or its licensors do not warrant that this design will meet" at 6329.01,-718 h45
  text ".PRJ_Engineer" at 11393.5,-768.49 h70
  text ".PCB_Layout" at 12899,-768.49 h70
  text "the specifications, will be suitable for your application or fit for any particular purpose, or will operate in" at 6329.01,-830.67 h45
  text ".Layer_Name" at 577,-858.49 h60
  text "ALTIUM DESIGNER VERSION:" at 12848.5,-923.5 h45
  text "an implementation. TI and/or its licensors do not warrant that the design is production worthy. You should" at 6329.01,-943.33 h45
  text "completely validate and test your design implementation to confirm the system functionality for your application." at 6374,-1056 h45
  text ".print_Scale" at 11393.5,-1056.83 h70
  text ".Application_BuildNumber" at 12899,-1056.83 h70
  text "1" at 739.84,-1263.5 h70
  text "2" at 3235.5,-1263.5 h70
  text "3" at 5724.84,-1263.5 h70
  text "4" at 8231.51,-1263.5 h70
  text "5" at 10730.5,-1263.5 h70
  text "6" at 13235.5,-1263.5 h70
M10 Fab Notes:
  drawing of 189 lines, arcs and shapes, not listed
  text "DESIGN INFORMATION" at 12382.02,6356.17 h60
  text "MIN. TRACK WIDTH:" at 11737.46,6224.05 h60
  text "8" at 12833.7,6224.05 h60
  text "MIL" at 12988.46,6224.05 h60
  text "MIN. CLEARANCE:" at 11737.46,6099.92 h60
  text "0.2" at 12773.7,6099.93 h60
  text "mm" at 12988.46,6099.92 h60
  text "MIN. VIA PAD SIZE:" at 11737.46,5975.8 h60
  text "24" at 12803.71,5975.8 h60
  text "MIL" at 12988.46,5975.8 h60
  text "0.05mm (2MIL)" at 12432.46,5845.9 h60
  text "MINIMUM ANNULAR RING" at 11408.23,5837.67 h60
  text "EXTERNAL" at 13140.46,5837.67 h60
  text "PER" at 11608.23,5727.55 h60
  text "IPC-D-275 CLASS 2 LEVEL C" at 11828.23,5727.54 h60
  text "MIL, HOLES" at 13316.46,5627.07 h60
  text "+/-" at 12924,5618.48 h60
  text "+/-" at 13778,5618.48 h60
  text "REGISTRATION TOLERANCES:" at 11408.23,5617.42 h60
  text "METAL" at 12608,5617.42 h60
  text "5" at 13184.2,5617.42 h60
  text "3" at 14017.2,5617.42 h60
  text "MIL" at 14133.46,5617.42 h60
  text "HOLE SIZE TOLERANCE (UNLESS OTHERWISE SPECIFIED):" at 11408.23,5519.1 h60
  text "+/-" at 13778,5516.23 h60
  text "3" at 14017.2,5515.17 h60
  text "MIL" at 14133.46,5515.17 h60
  text "MATERIAL:" at 11333.46,5377.52 h60
  text "FR-4 High Tg" at 12319.9,5249 h60
  text "X" at 12175.46,5241.01 h60
  text "FR-408" at 11754.46,5236.49 h60
  text "OTHER" at 13242.46,5236.49 h60
  text "62 MIL (1.6mm) +/-10%" at 12074.56,5093.46 h60
  text "X" at 11954.46,5091.01 h60
  text "THICKNESS:" at 11408.23,5085.24 h60
  text "OTHER" at 13359.46,5085.24 h60
  text "TOLERANCE:" at 11408.23,4946.92 h60
  text "X" at 12256.46,4946.92 h60
  text "ANSI IPC-6012 TYPE 3 CLASS 2" at 12434.48,4946.92 h60
  text "OTHER +/-" at 12434.46,4802.73 h60
  text "BOW & TWIST:" at 11408.23,4657.54 h60
  text "X" at 12256.46,4657.54 h60
  text "ANSI IPC-6012 TYPE 3 CLASS 2" at 12434.48,4657.54 h60
  text "OTHER +/-" at 12434.46,4510.85 h60
  text "DRILLING:" at 11333.46,4380.23 h60
  text "NC_DRILL FILES" at 13094.46,4275.04 h60
  text "REFERENCE:" at 11408.23,4271.1 h60
  text "X" at 12065.46,4271.01 h60
  text "AS SHOWN" at 12243.46,4271.1 h60
  text "X" at 12966.46,4271.1 h60
  text "OTHER" at 13392.46,4128.85 h60
  text "PTH COPPER THICKNESS:" at 11407.91,4125.32 h60
  text "X" at 12547.14,4125.32 h60
  text "20-30 um" at 12675.14,4125.32 h60
  text "BOARD FINISH:" at 11333.46,3977.73 h60
  text "SILKSCREEN:" at 11488.68,3867.6 h60
  text "X" at 12446.46,3867.6 h60
  text "TOP" at 12563.46,3867.6 h60
  text "X" at 12956.46,3867.6 h60
  text "BOTTOM" at 13074.46,3867.6 h60
  text "SILKSCREEN COLOR:" at 11488.68,3712.41 h60
  text "X" at 12445.46,3712.41 h60
  text "WHITE" at 12563.46,3712.41 h60
  text "OTHER" at 13074.46,3712.41 h60
  text "X" at 12576.46,3568.96 h60
  text "GREEN" at 12694.46,3568.96 h60
  text "OTHER" at 13312.46,3568.96 h60
  text "SOLDER RESIST COLOR:" at 11488.68,3562.1 h60
  text "MATTE" at 12694.46,3414.71 h60
  text "X" at 13170,3415 h60
  text "SEMI-GLOSS" at 13312,3414.07 h60
  text "IMMERSION GOLD (ENIG)" at 12394.46,3241.94 h60
  text "ENEPIG" at 13732,3234.72 h60
  text "SURFACE FINISH:" at 11333.46,3233.72 h60
  text "X" at 12216.46,3233.72 h60
  text "IMM. TIN/SILVER OR EQUIV" at 11663,3096.4 h60
  text "OTHER" at 13094.46,3092.47 h60
  text "ARRAY/PANEL:" at 11333.46,2937.09 h60
  text "CUT AND TRIM PER M1 BOARD OUTLINE" at 12394.46,2928.87 h60
  text "N.C. ROUTE" at 12394.46,2792.9 h60
  text "V. SCORE" at 13260.46,2792.9 h60
  text "X" at 12210,2785 h60
  text "CERTIFICATION:" at 11333.46,2663.77 h60
  text "MATERIALS AND WORKMANSHIP FOR ALL PCBS" at 12058.46,2663.77 h60
  text "TO MEET OR EXCEED THE REQUIREMENTS OF:" at 12058.46,2569.71 h60
  text "X" at 11695.97,2441.08 h60
  text "ANSI IPC-A-600F CLASS ->" at 11823.96,2441.08 h60
  text "X" at 13471.97,2441.08 h60
  text "2" at 13581.96,2441.08 h60
  text "1" at 13266.96,2439.58 h60
  text "3" at 13935.96,2439.58 h60
  text "X" at 12507.97,2293.39 h60
  text "RoHS" at 12635.96,2293.39 h60
  text "OTHER" at 13280.36,2293.39 h60
  text "PER ORDER" at 13677.42,2293.39 h60
  text "ALL BOARDS MUST MEET OR EXCEED UL94-V0 REQUIREMENTS." at 11361,2139.57 h60
  text "PCB MUST BEAR THE UL94V-0 UL REGISTERED MATERIAL ID NUMBER" at 11361,2023.5 h60
  text "ADDITIONAL REQUIREMENTS:" at 11333.46,1854.08 h60
  text "MICROSECTION:" at 11408.23,1746.95 h60
  text "YES" at 12313.96,1746.95 h60
  text "REQUIRED" at 13175.46,1602.62 h60
  text "BARE BOARD ELEC. TEST:" at 11408.23,1599.76 h60
  text "NONE" at 12713.96,1599.76 h60
  text "X" at 13057.46,1599.76 h60
  text "PER ORDER" at 13767.46,1599.76 h60
  text "XX MIL VIAS REQUIRE NON-CONDUCTIVE FILL AND PLANARIZE" at 11576.38,1394.82 h59
  text "XX MIL VIAS REQUIRE CONDUCTIVE FILL AND PLANARIZE" at 11584.38,1290.84 h60
  text "OUTER XX MIL VIAS REQUIRE 50 OHM SINGLE-ENDED IMPEDANCE" at 11583.39,1127.46 h58
  text "LAYER 2 & 3 (INNER LAYERS) XX MIL WIDE, XX MIL SPACE / TRACES REQUIRE 100 OHM DIFFERENTIAL IMPEDANCE" at 11575.39,891.74 h60
  text ".Layer_Name" at 577,-858.49 h60
M11 Gerber Information:
  lines w10: -292,-930.17 6308,-930.17 ; -292,-726.83 6310,-726.83 ; -292,-523.5 -292,-1133.5 3713,-1133.5 6310,-1133.5 6310,-523.5 -291.5,-523.5 -291.5,-1133.5 1284,-1133.5 ; 2173,-1133.5 2173,-523.5 ; 3440,-726.83 3440,-523.5 ; 4280,-726.83 4280,-523.5 ; 4902,-1140 4902,-937.17
  text "ALL ARTWORK VIEWED FROM TOP SIDE" at -228.5,-655.67 h60
  text "BOARD #:" at 2248,-655.67 h60
  text ".PRJ_Number" at 2793.5,-655.67 h60
  text "REV:" at 3638,-655.67 h60
  text ".PCB_Rev" at 3929.5,-655.67 h60
  text "SVN REV:" at 4476,-655.67 h60
  text ".VersionControl_RevNumber" at 4982,-655.67 h60
  text "LAYER NAME =" at -228.5,-858.49 h60
  text "TID #:" at 2248,-859 h60
  text ".TID" at 2793.5,-859 h60
  text "PLOT NAME =" at -228.5,-1064.34 h60
  text ".plot_File_Name" at 577,-1064.34 h60
  text "GENERATED    :" at 2250,-1064.34 h60
  text ".Print_Date" at 3119.5,-1064.34 h60
  text ".Print_Time" at 3848.5,-1064.34 h60
  text "TEXAS INSTRUMENTS" at 5113,-1064.34 h60
M12 Stackup:
  drawing of 191 lines, arcs and shapes, not listed
  text "Layer" at 9625.34,7725 h60
  text "Name" at 10035.26,7725 h60
  text "Material" at 10965,7725 h60
  text "Thickness" at 11824.77,7725 h60
  text "Constant" at 12474.6,7725 h60
  text "Board Layer Stack" at 13044.46,7725 h60
  text "1" at 9625.34,7605 h60
  text "Top Overlay" at 10035.26,7605 h60
  text "2" at 9625.34,7485 h60
  text "Top Solder" at 10035.26,7485 h60
  text "Solder Resist" at 10965,7485 h60
  text "0.40mil" at 11824.77,7485 h60
  text "3.5" at 12474.6,7485 h60
  text "3" at 9625.34,7365 h60
  text "Top Layer" at 10035.26,7365 h60
  text "Copper" at 10965,7365 h60
  text "1.40mil" at 11824.77,7365 h60
  text "4" at 9625.34,7245 h60
  text "Dielectric1" at 10035.26,7245 h60
  text "FR-4" at 10965,7245 h60
  text "59.20mil" at 11824.77,7245 h60
  text "4.8" at 12474.6,7245 h60
  text "5" at 9625.34,7125 h60
  text "Bottom Layer" at 10035.26,7125 h60
  text "Copper" at 10965,7125 h60
  text "1.40mil" at 11824.77,7125 h60
  text "6" at 9625.34,7005 h60
  text "Bottom Solder" at 10035.26,7005 h60
  text "Solder Resist" at 10965,7005 h60
  text "0.40mil" at 11824.77,7005 h60
  text "3.5" at 12474.6,7005 h60
  text "7" at 9625.34,6885 h60
  text "Bottom Overlay" at 10035.26,6885 h60
  text ".Layer_Name" at 577,-858.49 h60
M13 Component Bodies Top:
  text ".Layer_Name" at 577,-858.49 h60
M14 Component Bodies Bottom:
  text ".Layer_Name" at 577,-858.49 h60
M15 Courtyards Top:
  text ".Layer_Name" at 577,-858.49 h60
M16 Courtyards Bottom:
  text ".Layer_Name" at 577,-858.49 h60
Drill Drawing:
  circle w10: c4608.72,1901.96 r27.63
  lines w10: 4581.09,1128.42 4581.09,1142.23 4594.9,1156.04 4581.09,1169.86 4581.09,1183.67 4594.9,1183.67 4608.72,1169.86 4622.53,1183.67 4636.34,1183.67 4636.34,1169.86 4622.53,1156.04 4636.34,1142.23 4636.34,1128.42 4622.53,1128.42 4608.72,1142.23 4594.9,1128.42 4581.09,1128.42 ; 4581.09,1307.99 4636.34,1307.99 4608.72,1252.74 4581.09,1307.99 ; 4581.09,1390.87 4594.9,1390.87 4594.9,1377.06 4622.53,1377.06 4622.53,1390.87 4636.34,1390.87 4636.34,1418.5 4622.53,1418.5 4622.53,1432.31 4594.9,1432.31 4594.9,1418.5 4581.09,1418.5 4581.09,1390.87 ; 4581.09,1501.38 4608.72,1515.19 4636.34,1501.38 4622.53,1529 4636.34,1556.63 4608.72,1542.82 4581.09,1556.63 4594.9,1529 4581.09,1501.38 ; 4581.09,1653.32 4608.72,1625.7 4636.34,1653.32 4608.72,1680.95 4581.09,1653.32 ; 4581.09,1750.02 4636.34,1750.02 4636.34,1805.27 4581.09,1805.27 4581.09,1750.02 ; 4581.09,2012.47 4594.9,2012.47 4608.72,1998.66 4622.53,2012.47 4636.34,2012.47 4622.53,2026.28 4636.34,2040.1 4622.53,2040.1 4608.72,2053.91 4594.9,2040.1 4581.09,2040.1 4594.9,2026.28 4581.09,2012.47
  lines w12: 4531,1091.12 7762.49,1091.12 ; 4531,2085.68 7762.49,2085.68 ; 4868.86,966.8 4868.86,2210 ; 5200.86,966.8 5200.86,2210 ; 5837.43,966.8 5837.43,2210 ; 6096.57,966.8 6096.57,2210 ; 6471.72,966.8 6471.72,2210 ; 7196.05,966.8 7196.05,2210 ; 4531,966.8 7762.49,966.8 7762.49,2210 4531,2210 4531,966.8
  text "Symbol" at 4605.59,2122.98 h72
  text "Quantity" at 4906.16,2122.98 h72
  text "Finished Hole Size" at 5238.16,2122.98 h72
  text "Plated" at 5874.72,2122.98 h72
  text "Hole Type" at 6133.86,2122.98 h72
  text "Drill Layer Pair" at 6509.02,2122.98 h72
  text "Hole Tolerance" at 7233.35,2122.98 h72
  text "1" at 4906.16,1998.66 h60
  text "149.61mil (3.800mm)" at 5238.16,1998.66 h60
  text "NPTH" at 5874.72,1998.66 h60
  text "Round" at 6133.86,1998.66 h60
  text "Top Layer - Bottom Layer" at 6509.02,1998.66 h60
  text "29" at 4906.16,1874.34 h60
  text "16.00mil (0.406mm)" at 5238.16,1874.34 h60
  text "PTH" at 5874.72,1874.34 h60
  text "Round" at 6133.86,1874.34 h60
  text "Top Layer - Bottom Layer" at 6509.02,1874.34 h60
  text "9" at 4906.16,1750.02 h60
  text "40.00mil (1.016mm)" at 5238.16,1750.02 h60
  text "PTH" at 5874.72,1750.02 h60
  text "Round" at 6133.86,1750.02 h60
  text "Top Layer - Bottom Layer" at 6509.02,1750.02 h60
  text "2" at 4906.16,1625.7 h60
  text "46.00mil (1.168mm)" at 5238.16,1625.7 h60
  text "PTH" at 5874.72,1625.7 h60
  text "Round" at 6133.86,1625.7 h60
  text "Top Layer - Bottom Layer" at 6509.02,1625.7 h60
  text "9" at 4906.16,1501.38 h60
  text "50.00mil (1.270mm)" at 5238.16,1501.38 h60
  text "PTH" at 5874.72,1501.38 h60
  text "Round" at 6133.86,1501.38 h60
  text "Top Layer - Bottom Layer" at 6509.02,1501.38 h60
  text "2" at 4906.16,1377.06 h60
  text "55.12mil (1.400mm)" at 5238.16,1377.06 h60
  text "PTH" at 5874.72,1377.06 h60
  text "Round" at 6133.86,1377.06 h60
  text "Top Layer - Bottom Layer" at 6509.02,1377.06 h60
  text "2" at 4906.16,1252.74 h60
  text "64.96mil (1.650mm)" at 5238.16,1252.74 h60
  text "PTH" at 5874.72,1252.74 h60
  text "Round" at 6133.86,1252.74 h60
  text "Top Layer - Bottom Layer" at 6509.02,1252.74 h60
  text "6" at 4906.16,1128.42 h60
  text "86.61mil (2.200mm)" at 5238.16,1128.42 h60
  text "PTH" at 5874.72,1128.42 h60
  text "Round" at 6133.86,1128.42 h60
  text "Top Layer - Bottom Layer" at 6509.02,1128.42 h60
  text "60 Total" at 4906.16,1004.1 h60
  text ".Layer_Name" at 577,-858.49 h60
M17 Embedded Cavity:
  text ".Layer_Name" at 577,-858.49 h60
M18 Embedded Assembly:
  text ".Layer_Name" at 577,-858.49 h60
M19 Embedded Keepout:
  text ".Layer_Name" at 577,-858.49 h60

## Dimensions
0,0 to 2750,0 on M2 Board Dimensions
0,0 to 0,3000 on M2 Board Dimensions
0,-400 to 1000,-400 on M2 Board Dimensions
